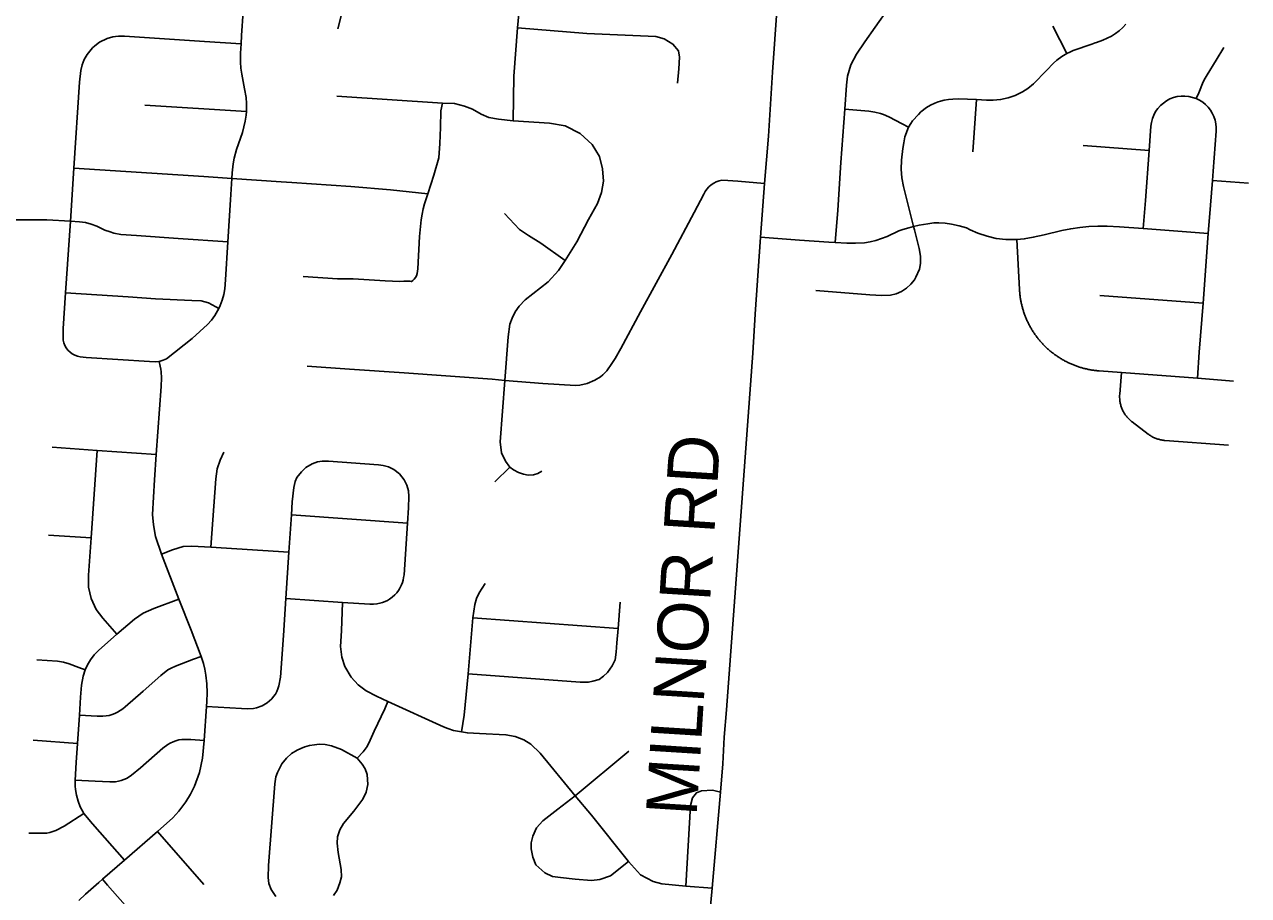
# Model space of a CAD drawing. Extents: x 1880545 to 1948545, y 79309 to 723051.
# Drawn here: x 1895523 to 1902271, y 698000 to 702803 of the extents above; entities that cross this region are included whole.
import ezdxf

# ---------------------------------------------------------------- set-up
doc = ezdxf.new("R2010")
doc.units = 0
for name, color, linetype in [('GM_X_County_Road', 7, 'Continuous'), ('GM_X_Township_Road', 7, 'Continuous'), ('SH_Text', 7, 'Continuous')]:
    doc.layers.add(name, color=color, linetype=linetype)

msp = doc.modelspace()

# ---------------------------------------------------------------- linework, layer by layer
at = {"layer": 'GM_X_County_Road'}
for points in [[(1899603.4, 701926.9), (1899623.9, 702188), (1899647, 702540.4), (1899672.6, 702904.2)], [(1899030.5, 694138.3), (1899059.6, 694602.2), (1899090.3, 695133.9), (1899173.7, 696143.5), (1899230.4, 697129.9), (1899314.5, 698039.5), (1899359.1, 698569.6), (1899373.2, 698725.3), (1899381.1, 698873.1), (1899393.7, 699024.1), (1899474.7, 700118.2), (1899537.6, 700991.2), (1899551.1, 701205.8), (1899581.2, 701630.1), (1899603.4, 701926.9)]]:
    msp.add_lwpolyline(points, dxfattribs=at)
at = {"layer": 'GM_X_Township_Road'}
for p, q in [((1901269.3, 702643.2), (1901191.6, 702794.5)), ((1896187.3, 702358.7), (1896746.2, 702323.2)), ((1900750.9, 702100.6), (1900771.5, 702389.9)), ((1901358.7, 702135), (1901722.7, 702107.4)), ((1896666.1, 701952.9), (1896937.4, 701935.8)), ((1902071.3, 701943.6), (1902270.7, 701928.5)), ((1895444.7, 701725.4), (1895612.2, 701726.5)), ((1901451.5, 701308.7), (1902019.9, 701265.6)), ((1901988.6, 700851.8), (1901999.5, 700996.4)), ((1898115.3, 700280.2), (1898199.4, 700362.2)), ((1896994.4, 700098.3), (1897633.8, 700053.1)), ((1895654.7, 699987.1), (1895890.7, 699971.8)), ((1897994.7, 699531), (1898795.4, 699472.5)), ((1895814.8, 698837.3), (1895571.8, 698855.5)), ((1898558.2, 698548.5), (1898855.5, 698794.8)), ((1896256.2, 698351.9), (1896511.3, 698059.9))]:
    msp.add_line(p, q, dxfattribs=at)
for points in [[(1897251.3, 702779.6), (1897275.9, 702879.9), (1897277.1, 703062.6), (1897287.8, 703187.1), (1897305.4, 703355.7)], [(1898217.4, 702271.2), (1898221.1, 702518.1), (1898241, 702785.2), (1898258.4, 702980.7), (1898269.4, 703137.3), (1898281.1, 703291.3)], [(1899991.3, 701600.3), (1900005.9, 701779.6), (1900022.7, 702042.4), (1900044.5, 702336.3), (1900054.3, 702469.1), (1900060.6, 702518.1), (1900079, 702581.1), (1900109.2, 702639.5), (1900155.1, 702707.8), (1900213.4, 702787.5), (1900288.8, 702895.4)], [(1896265.7, 700945.4), (1896287, 700951.7), (1896305.2, 700960), (1896447.4, 701071.2), (1896532.4, 701147.8), (1896553.2, 701172.4), (1896571.7, 701198.9), (1896593.9, 701236), (1896602.4, 701252.9), (1896613.3, 701282.4), (1896621.5, 701313.9), (1896627, 701345.8), (1896631.7, 701394.5), (1896643.6, 701605), (1896659.6, 701836.7), (1896666.1, 701952.9), (1896667.9, 701984.4), (1896673.2, 702033.7), (1896679.1, 702066.3), (1896691.8, 702114.3), (1896724.5, 702207.4), (1896740.5, 702270.3), (1896744.8, 702302.4), (1896746.2, 702323.2), (1896746.8, 702367.4), (1896744.3, 702399.8), (1896736.8, 702448), (1896720.8, 702528.8), (1896716.3, 702561.6), (1896713.9, 702594.6), (1896713.9, 702644.2), (1896717.1, 702696.8), (1896719.9, 702742.8), (1896729.4, 702873.9)], [(1898241, 702785.2), (1898623.5, 702752.7), (1899003.6, 702736.7), (1899048.9, 702723.5), (1899097.9, 702695.1), (1899128.1, 702657.4), (1899133.8, 702623.5), (1899130, 702559.3), (1899122.4, 702480)], [(1900424.8, 701689.3), (1900368.8, 701908.7), (1900359.5, 701956.6), (1900356.3, 702005.3), (1900358.3, 702054.1), (1900364.8, 702119), (1900369.7, 702151.3), (1900376.7, 702183.1), (1900396.3, 702236.1), (1900408.5, 702257.8), (1900418, 702271.1), (1900450.8, 702307.3), (1900463.7, 702320.5), (1900494.9, 702344.5), (1900516.7, 702357.8), (1900542, 702369.1), (1900559.4, 702376.3), (1900573, 702380.7), (1900592.2, 702385.8), (1900617.4, 702390.1), (1900640.8, 702392.1), (1900671.9, 702392.6), (1900771.5, 702389.9), (1900826.3, 702385.9), (1900862.4, 702385.2), (1900904.2, 702389.1), (1900945.2, 702397.9), (1900984.9, 702411.6), (1901024.4, 702430.9), (1901054.7, 702450.3), (1901085.8, 702475.4), (1901157.5, 702549.7), (1901196.3, 702590.1), (1901214.4, 702606.9), (1901241.7, 702627.1), (1901269.3, 702643.2), (1901289.9, 702652.8), (1901304.8, 702658.7), (1901406.6, 702695.4), (1901425.1, 702702), (1901431.8, 702704.4), (1901468, 702717.5), (1901492.1, 702727.3), (1901515.2, 702739.3), (1901537.2, 702753.1), (1901558, 702768.9), (1901577.2, 702786.3), (1901594.9, 702805.4)], [(1896265.7, 700945.4), (1896244.3, 700943.4), (1896213, 700943.9), (1895862.6, 700966.3), (1895830.6, 700970), (1895815.3, 700973.7), (1895800.7, 700979.3), (1895786.8, 700986.8), (1895774.1, 700996), (1895762.7, 701006.8), (1895753.1, 701019.1), (1895745.6, 701032.7), (1895740.2, 701047.3), (1895737.1, 701062.7), (1895735.8, 701078.6), (1895735.6, 701094.7), (1895736.7, 701127.2), (1895749.9, 701323.6), (1895776.3, 701717.8), (1895795.6, 702010.4), (1895826.2, 702484.4), (1895833.4, 702549.3), (1895840.5, 702580.4), (1895851.9, 702610), (1895867.9, 702637.7), (1895898.4, 702675), (1895910.1, 702685.9), (1895935.8, 702704.8), (1895979.1, 702725.6), (1896009.9, 702734.4), (1896025.7, 702737.1), (1896041.6, 702738.8), (1896073.8, 702739), (1896514.8, 702709.6), (1896717.1, 702696.8)], [(1901982.6, 702394.2), (1901996.3, 702426.6), (1902021.6, 702486.3), (1902031.1, 702506.7), (1902042.2, 702526.3), (1902091.7, 702606.8), (1902133.8, 702675.4)], [(1897244.1, 702408.3), (1897827.6, 702369), (1897894.3, 702367.8), (1897948, 702353.5), (1897993.3, 702336.8), (1898041, 702308.1), (1898082.7, 702290.3), (1898136.4, 702280.7), (1898217.4, 702271.2), (1898416.5, 702259.3), (1898502.9, 702244.5), (1898585.8, 702201.6), (1898652.5, 702141.3)], [(1897650.1, 701387.1), (1897655.9, 701385.2), (1897664.2, 701391), (1897671.5, 701397.7), (1897678.6, 701407), (1897683.5, 701417.5), (1897687.7, 701430), (1897690.2, 701442.9), (1897691, 701455.7), (1897701.2, 701634.7), (1897705.4, 701688.9), (1897709.9, 701726), (1897715.2, 701757.4), (1897721.3, 701786.5), (1897729.1, 701814.7), (1897746.5, 701868.9), (1897780.4, 701971.2), (1897806.4, 702068.1), (1897812.1, 702145.9), (1897815.7, 702234.2), (1897818.1, 702327.2), (1897827.6, 702369)], [(1901690.1, 701677.7), (1901701.9, 701833.2), (1901722.7, 702107.4), (1901732.8, 702242.1), (1901735.7, 702263.2), (1901741.1, 702283.8), (1901748.8, 702303.7), (1901758.8, 702322.5), (1901771, 702340), (1901785.2, 702355.9), (1901801.2, 702370), (1901818.7, 702382.2), (1901837.5, 702392.2), (1901857.4, 702399.9), (1901878, 702405.2), (1901899.2, 702408), (1901920.5, 702408.3), (1901941.7, 702406.1), (1901962.5, 702401.3), (1901982.6, 702394.2)], [(1902060.8, 701806.1), (1902071.3, 701943.6), (1902075.1, 701994.7), (1902091.8, 702214.9), (1902092.2, 702235.2), (1902090.3, 702255.5), (1902086.1, 702275.5), (1902079.7, 702294.8), (1902071.1, 702313.3), (1902060.5, 702330.7), (1902048, 702346.8), (1902033.8, 702361.3), (1902018, 702374.2), (1902000.8, 702385.2), (1901982.6, 702394.2)], [(1900044.5, 702336.3), (1900177.6, 702325.5), (1900210.2, 702320.4), (1900242.2, 702312.4), (1900257.7, 702306.9), (1900287.8, 702293.4), (1900360.8, 702254.9), (1900396.3, 702236.1)], [(1898374.4, 700339.9), (1898353.7, 700326.8), (1898329.9, 700320.2), (1898300.3, 700317.5), (1898273.3, 700322.7), (1898247, 700332.6), (1898218.5, 700346.3), (1898199.4, 700362.2), (1898175, 700395.3), (1898153, 700440.5), (1898144.8, 700500.9), (1898171.5, 700839.7), (1898190.1, 701081), (1898199.4, 701150.6), (1898211, 701184.3), (1898228.4, 701217.9), (1898250.4, 701249.2), (1898284.1, 701284), (1898409.4, 701383.8), (1898466.2, 701446.5), (1898504, 701501.4), (1898567.8, 701605.2), (1898632.8, 701727.6), (1898681.5, 701816.4), (1898704.2, 701876.7), (1898714.6, 701938.8), (1898709.2, 702007), (1898693, 702075.1), (1898652.5, 702141.3)], [(1895795.6, 702010.4), (1896512.3, 701964), (1896666.1, 701952.9)], [(1896937.4, 701935.8), (1896997.1, 701932.1), (1897321.6, 701909), (1897540.5, 701890.4), (1897746.5, 701868.9)], [(1897081.5, 700918.3), (1897314.2, 700902.1), (1897616.9, 700881.4), (1898101.9, 700846.6), (1898171.5, 700839.7), (1898381.3, 700823.2), (1898560.7, 700812.7), (1898584.6, 700814.6), (1898625.2, 700823.9), (1898667.4, 700841.6), (1898698.2, 700860), (1898710.8, 700870.4), (1898733, 700893.6), (1898761.8, 700933), (1898779.3, 700960.8), (1898809.9, 701016.5), (1898918.5, 701217.7), (1899091.4, 701534.4), (1899214, 701766.5), (1899267.5, 701868.1), (1899276, 701882.1), (1899285.5, 701895.4), (1899296.4, 701907.6), (1899308.9, 701918.2), (1899322.4, 701927.6), (1899336.7, 701935.7), (1899352, 701941.3), (1899368.1, 701943.8), (1899399.7, 701943.2), (1899454.9, 701939.6), (1899603.4, 701926.9)], [(1898168.7, 701761.3), (1898252.8, 701672.5), (1898301, 701639.4), (1898368.8, 701596.8), (1898504, 701501.4)], [(1901999.5, 700996.4), (1902019.9, 701265.6), (1902049.1, 701650.5), (1902060.8, 701806.1)], [(1895612.2, 701726.5), (1895645.7, 701726.7), (1895776.3, 701717.8), (1895825.8, 701714.3), (1895858.8, 701710.5), (1895891.3, 701702.8), (1895922.4, 701690.8), (1895966.9, 701669.5), (1895994.9, 701658.7), (1896016.5, 701652.3), (1896055.2, 701645.2), (1896141.4, 701638.8), (1896370.5, 701623.4), (1896643.6, 701605)], [(1899581.2, 701630.1), (1899795.7, 701613.2), (1899958, 701602.3), (1899991.3, 701600.3), (1900055.6, 701596.4), (1900104.3, 701596.3), (1900153.1, 701599.7), (1900185.2, 701605), (1900216.8, 701612.7), (1900278, 701634.8), (1900343.4, 701664.7), (1900365.6, 701673.4), (1900398.7, 701682.4), (1900424.8, 701689.3), (1900455, 701696), (1900502.8, 701703.4), (1900535.6, 701708.4), (1900552.6, 701708.5)], [(1899885.7, 701335.2), (1900182.7, 701312.1), (1900248.5, 701308), (1900297, 701310.9), (1900328.4, 701318.3), (1900358, 701330.8), (1900384.9, 701348.4), (1900408.8, 701370.2), (1900428.9, 701395.7), (1900437.5, 701409.6), (1900457.1, 701454.2), (1900463.1, 701485.4), (1900462.3, 701525.5), (1900455.9, 701568.1), (1900429.7, 701670.4), (1900424.8, 701689.3)], [(1900552.6, 701708.5), (1900564, 701708.6), (1900599.1, 701706.5), (1900633.1, 701702.2), (1900676.5, 701693.1), (1900715.9, 701681.3), (1900735.7, 701670.9), (1900778.1, 701652.8), (1900830.1, 701634.9), (1900878.8, 701623.7), (1900933.4, 701617.1), (1900993.3, 701616.7), (1901034.4, 701620.6), (1901084.2, 701630), (1901143.9, 701643.8)], [(1901143.9, 701643.8), (1901241.4, 701666.3), (1901290.7, 701676.3), (1901340.5, 701683.9), (1901390.6, 701689), (1901440.8, 701691.5), (1901491.2, 701691.5), (1901560, 701687.6), (1901690.1, 701677.7), (1902049.1, 701650.5)], [(1900993.3, 701616.7), (1901008.3, 701340.8), (1901008.9, 701331.3), (1901009.3, 701326.3), (1901009.7, 701321.3), (1901010.2, 701316.3), (1901010.8, 701311.4), (1901011.4, 701306.4), (1901012, 701301.5), (1901012.7, 701296.5), (1901013.5, 701291.6), (1901014.3, 701286.6), (1901015.2, 701281.7), (1901016.1, 701276.8), (1901017.1, 701271.9), (1901018.1, 701267), (1901019.2, 701262.1), (1901020.3, 701257.2), (1901021.5, 701252.4), (1901022.7, 701247.5), (1901024, 701242.7), (1901025.3, 701237.9), (1901026.7, 701233.1), (1901028.1, 701228.3), (1901029.6, 701223.5), (1901031.1, 701218.7), (1901032.7, 701214), (1901034.3, 701209.3), (1901036, 701204.6), (1901037.7, 701199.9), (1901039.5, 701195.2), (1901041.3, 701190.5), (1901043.2, 701185.9), (1901045.1, 701181.3), (1901047.1, 701176.7), (1901049.1, 701172.1), (1901051.2, 701167.6), (1901053.3, 701163.1), (1901055.5, 701158.5), (1901057.7, 701154.1), (1901060, 701149.6), (1901062.3, 701145.2), (1901064.6, 701140.8), (1901067, 701136.4), (1901069.5, 701132), (1901072, 701127.7), (1901074.5, 701123.4), (1901077.1, 701119.1), (1901079.7, 701114.8), (1901082.4, 701110.6), (1901085.1, 701106.4), (1901087.8, 701102.2), (1901090.6, 701098.1), (1901093.5, 701094), (1901096.4, 701089.9), (1901099.3, 701085.9), (1901102.3, 701081.8), (1901105.3, 701077.8), (1901108.4, 701073.9), (1901111.5, 701070), (1901114.6, 701066.1), (1901117.8, 701062.2), (1901121, 701058.4), (1901124.3, 701054.6), (1901127.6, 701050.9), (1901130.9, 701047.1), (1901134.3, 701043.5), (1901137.7, 701039.8), (1901141.2, 701036.2), (1901144.7, 701032.6), (1901148.2, 701029.1), (1901151.8, 701025.6), (1901155.4, 701022.1), (1901159, 701018.7), (1901162.7, 701015.3), (1901166.4, 701012), (1901170.2, 701008.7), (1901174, 701005.4), (1901177.8, 701002.2), (1901181.6, 700999), (1901185.5, 700995.8), (1901189.4, 700992.7), (1901193.4, 700989.6), (1901197.4, 700986.6), (1901201.4, 700983.6), (1901205.4, 700980.7), (1901209.5, 700977.8), (1901213.6, 700975), (1901217.7, 700972.1), (1901221.9, 700969.4), (1901226.1, 700966.7), (1901230.3, 700964), (1901234.6, 700961.4), (1901238.9, 700958.8), (1901243.2, 700956.2), (1901247.5, 700953.7), (1901251.9, 700951.3), (1901256.2, 700948.9), (1901260.6, 700946.5), (1901265.1, 700944.2), (1901269.5, 700941.9), (1901274, 700939.7), (1901278.5, 700937.5), (1901283, 700935.4), (1901287.6, 700933.3), (1901292.2, 700931.3), (1901296.8, 700929.3), (1901301.4, 700927.4), (1901306, 700925.5), (1901310.6, 700923.7), (1901315.3, 700921.9), (1901320, 700920.2), (1901324.7, 700918.5), (1901329.4, 700916.8), (1901334.2, 700915.3), (1901338.9, 700913.7), (1901343.7, 700912.2), (1901348.5, 700910.8), (1901353.3, 700909.4), (1901358.1, 700908.1), (1901363, 700906.8), (1901367.8, 700905.6), (1901372.7, 700904.4), (1901377.5, 700903.2), (1901382.4, 700902.2), (1901387.3, 700901.1), (1901392.2, 700900.2), (1901397.1, 700899.2), (1901402, 700898.4), (1901407, 700897.5), (1901411.9, 700896.8), (1901416.9, 700896), (1901421.8, 700895.4), (1901426.8, 700894.8), (1901431.8, 700894.2), (1901436.7, 700893.7), (1901441.7, 700893.2), (1901446.7, 700892.8), (1901569.8, 700883.5), (1901988.6, 700851.8), (1902188, 700836.7)], [(1897059.5, 701412.8), (1897249.3, 701401.2), (1897335.3, 701400.2), (1897511.5, 701388.8), (1897593.1, 701385.8), (1897614.2, 701387.1), (1897650.1, 701387.1)], [(1895749.9, 701323.6), (1896094.5, 701301), (1896245.1, 701291), (1896446.1, 701281), (1896496.7, 701278.4), (1896518.1, 701273.7), (1896537, 701267.9), (1896558.4, 701257.6), (1896577.2, 701246.2), (1896593.9, 701236)], [(1895823.6, 697971.8), (1895859.3, 698006.2), (1895933.4, 698071.5), (1895953.6, 698089), (1896074.6, 698194.1), (1896256.2, 698351.9), (1896340.4, 698428.6), (1896373.7, 698464.4), (1896412.8, 698516.4), (1896438, 698558.2), (1896460, 698601.9), (1896488.1, 698678.2), (1896504, 698757.8), (1896513.5, 698854.6), (1896526, 699041.5), (1896527.8, 699068.8), (1896529.4, 699117.8), (1896528, 699166.7), (1896522.9, 699215.3), (1896517.2, 699247.3), (1896509.5, 699278.9), (1896497, 699318), (1896441.8, 699463.4), (1896374.8, 699634.5), (1896277.9, 699882.4), (1896246.3, 699979.2), (1896234.2, 700043.3), (1896228.8, 700101), (1896239.8, 700291.3), (1896249.9, 700432.1), (1896276.9, 700805.9), (1896278.5, 700854.8), (1896277, 700887), (1896274.5, 700902.9), (1896271, 700918.7), (1896265.7, 700945.4)], [(1901569.8, 700883.5), (1901560.7, 700763.7), (1901560.3, 700756.4), (1901560.2, 700751.4), (1901560.3, 700746.4), (1901560.6, 700739.2), (1901561, 700734.2), (1901561.5, 700729.2), (1901562.2, 700724.3), (1901563, 700719.4), (1901564, 700714.5), (1901565.1, 700709.6), (1901566.3, 700704.7), (1901567.7, 700699.9), (1901569.2, 700695.2), (1901570.8, 700690.4), (1901572.6, 700685.8), (1901574.5, 700681.1), (1901576.6, 700676.6), (1901578.7, 700672.1), (1901581.1, 700667.6), (1901583.5, 700663.3), (1901586, 700659), (1901588.7, 700654.8), (1901591.5, 700650.6), (1901594.4, 700646.5), (1901597.4, 700642.6), (1901600.6, 700638.7), (1901603.8, 700634.9), (1901607.2, 700631.2), (1901610.6, 700627.6), (1901614.2, 700624.1), (1901617.9, 700620.6), (1901621.6, 700617.3), (1901625.5, 700614.2), (1901629.4, 700611.1), (1901717.3, 700544.4), (1901721.6, 700541.2), (1901725.7, 700538.4), (1901729.9, 700535.7), (1901734.2, 700533.1), (1901738.5, 700530.6), (1901742.9, 700528.2), (1901747.4, 700526), (1901751.9, 700523.9), (1901756.5, 700522), (1901761.2, 700520.1), (1901765.9, 700518.4), (1901770.6, 700516.9), (1901775.4, 700515.4), (1901780.3, 700514.1), (1901785.1, 700513), (1901790, 700512), (1901794.9, 700511.1), (1901799.9, 700510.4), (1901804.9, 700509.8), (1901809.8, 700509.3), (1902161.2, 700482.7)], [(1895676.3, 700471.6), (1895924.7, 700454.4), (1896249.9, 700432.1)], [(1896032.1, 699440.3), (1895954.8, 699528.8), (1895918.8, 699577.6), (1895890.4, 699636.7), (1895876.2, 699700.8), (1895875.7, 699766.4), (1895890.7, 699971.8), (1895924.7, 700454.4)], [(1896551.1, 699921.2), (1896577.6, 700297.8), (1896585.8, 700352.8), (1896601.1, 700399.7), (1896622.3, 700444.6)], [(1896994.4, 700098.3), (1896999.6, 700170.5), (1897007.3, 700250.1), (1897015.1, 700281.9), (1897025.4, 700304), (1897049.7, 700336.9), (1897073.4, 700359.3), (1897108.3, 700380.5), (1897139.3, 700390.4), (1897163.6, 700394.1), (1897199.6, 700394.1), (1897473.8, 700375.1), (1897499.5, 700371.4), (1897529.8, 700363.9), (1897559.1, 700349.7), (1897591.1, 700324.2), (1897616.4, 700291.6), (1897631.3, 700262.5), (1897639.3, 700231.1), (1897642.1, 700199.8), (1897640.3, 700138.5), (1897633.8, 700053.1), (1897615.3, 699768.8), (1897613, 699752.5), (1897610.1, 699738.7), (1897606.4, 699725.7), (1897601.1, 699712.3), (1897596.5, 699701.6), (1897590.7, 699691.2), (1897585.4, 699682.4), (1897575.5, 699669.6), (1897564.1, 699657.6), (1897549.6, 699644.2), (1897535.7, 699634.2), (1897523.6, 699626.9), (1897511.4, 699620.7), (1897497.2, 699615.3), (1897482.9, 699611.1), (1897466.3, 699608), (1897447.9, 699605.7), (1897427.1, 699606.3), (1897277, 699616.4), (1896963.8, 699637.9)], [(1896526, 699041.5), (1896720.2, 699030.1), (1896753.1, 699029.2), (1896785.9, 699031.7), (1896802.1, 699034.9), (1896833.2, 699045.6), (1896861.7, 699062.1), (1896874.5, 699072.4), (1896886.2, 699083.9), (1896896.7, 699096.5), (1896906, 699110.2), (1896913.9, 699124.6), (1896920.6, 699139.7), (1896926, 699155.2), (1896935.1, 699203.7), (1896950.1, 699433.8), (1896963.8, 699637.9), (1896981, 699892.5), (1896994.4, 700098.3)], [(1896277.9, 699882.4), (1896338.5, 699905.9), (1896397.3, 699924.2), (1896445.9, 699927.1), (1896551.1, 699921.2), (1896981, 699892.5)], [(1897932.2, 698901.6), (1897947.4, 698994), (1897969, 699222.6), (1897994.7, 699531), (1898005.4, 699604.5), (1898015.1, 699638.4), (1898029.6, 699668.6), (1898062.2, 699719.4)], [(1896074.6, 698194.1), (1895897.5, 698394.4), (1895851.2, 698452.6), (1895846.3, 698459.5), (1895830.4, 698489), (1895818.4, 698520.1), (1895809.4, 698552.2), (1895803.7, 698585.1), (1895802.4, 698601.8), (1895802.5, 698635), (1895807.7, 698733.6), (1895814.8, 698837.3), (1895825.6, 698994.8), (1895832.4, 699094), (1895837.9, 699159.7), (1895846.4, 699208.9), (1895857.9, 699243.8), (1895870.4, 699271.1), (1895887.5, 699299.8), (1895907.6, 699326.4), (1895930.6, 699350.6), (1896032.1, 699440.3), (1896129.1, 699523.5), (1896177.3, 699556.1), (1896235.6, 699581.7), (1896374.8, 699634.5)], [(1897277, 699616.4), (1897270.3, 699459.3), (1897265.9, 699373.8), (1897271.8, 699313.3), (1897289.5, 699261.7), (1897324.9, 699203.4), (1897363.2, 699161.4), (1897407.5, 699128.2), (1897463.5, 699099.5), (1897526.6, 699070.5), (1897832.2, 698929.9), (1897856.3, 698921), (1897888.3, 698909.2), (1897932.2, 698901.6), (1897964.9, 698895.9), (1898031.3, 698892.9), (1898177, 698886.1), (1898228.2, 698876.8), (1898276.1, 698857.6), (1898314.4, 698834), (1898366.7, 698784.4), (1898558.2, 698548.5), (1898648.2, 698442.5), (1898852, 698186.6), (1898918.9, 698114.4), (1898988.6, 698077.3), (1899035.8, 698064.3), (1899169.1, 698051.9), (1899314.5, 698039.5)], [(1897969, 699222.6), (1898586.7, 699176.9), (1898631.5, 699176.1), (1898655.6, 699181), (1898691.3, 699191.8), (1898714.6, 699208.4), (1898737.8, 699229.2), (1898763.6, 699265.7), (1898778.5, 699299), (1898785.1, 699341.3), (1898789.3, 699393.6), (1898795.4, 699472.5), (1898806.7, 699617.8)], [(1895825.6, 698994.8), (1895923, 698989.4), (1895955.5, 698988.8), (1895973, 698989.9), (1895989.6, 698992.9), (1896005.9, 698997.5), (1896021.6, 699003.7), (1896036.7, 699011.1), (1896064.8, 699029.3), (1896077.8, 699039.7), (1896176.5, 699126.6), (1896274.9, 699213.4), (1896314.1, 699243.4), (1896331.8, 699254.3), (1896356.5, 699264.7), (1896455.7, 699302.3), (1896497, 699318)], [(1895857.9, 699243.8), (1895822.4, 699257.7), (1895769.7, 699278.1), (1895738.1, 699286.5), (1895705.9, 699291.5), (1895591.4, 699299.3)], [(1897357.3, 698757.2), (1897390.1, 698791.7), (1897413.1, 698821.3), (1897429.6, 698855.8), (1897451.7, 698905.1), (1897509.2, 699030), (1897526.6, 699070.5)], [(1895802.5, 698635), (1895912.7, 698630.5), (1895993.5, 698626.4), (1896025.5, 698627.4), (1896041.2, 698629.8), (1896056.5, 698633.7), (1896071.5, 698639), (1896085.9, 698645.7), (1896099.7, 698653.6), (1896112.8, 698662.7), (1896162.5, 698704.7), (1896285.8, 698812.2), (1896312.5, 698832), (1896326.9, 698840.5), (1896342.2, 698847.7), (1896358, 698853.3), (1896374.3, 698857.3), (1896390.9, 698859.8), (1896407.6, 698860.7), (1896440.8, 698859.8), (1896513.5, 698854.6)], [(1897357.3, 698757.2), (1897270.5, 698804.6), (1897216.3, 698824.3), (1897180.2, 698832.6), (1897147.3, 698834.2), (1897121, 698830.9), (1897094.7, 698827.6), (1897068.4, 698819.4), (1897047.1, 698811.2), (1897025.9, 698800.6), (1896994.5, 698783.2), (1896968.2, 698757), (1896941.9, 698725.8), (1896917.3, 698678.1), (1896909.1, 698653.5), (1896902.5, 698615.7), (1896868, 698165.5), (1896866.4, 698099.8), (1896869.7, 698065.3), (1896882.8, 698032.4), (1896909.1, 697994.6)], [(1897225.8, 697999.6), (1897247.5, 698029.1), (1897262.3, 698070.2), (1897270.5, 698103.1), (1897268.9, 698142.5), (1897252.4, 698236.2), (1897247.5, 698288.7), (1897249.2, 698323.2), (1897260.7, 698362.7), (1897282, 698397.2), (1897339.5, 698464.5), (1897388.8, 698530.2), (1897406.9, 698569.7), (1897416.7, 698612.4), (1897411.8, 698666.6), (1897402, 698697.8), (1897385.5, 698724.1), (1897357.3, 698757.2)], [(1899169.1, 698051.9), (1899195.5, 698495.7), (1899204.8, 698537.8), (1899227.2, 698565.1), (1899254.5, 698577.8), (1899316, 698579.8), (1899359.1, 698569.6)], [(1898852, 698186.6), (1898754.2, 698108.5), (1898694.3, 698087.5), (1898649.1, 698082.9), (1898558.6, 698089.4), (1898478.4, 698098.6), (1898434.1, 698104.1), (1898392.5, 698124.4), (1898342.7, 698169.7), (1898326.1, 698210.3), (1898316, 698257.3), (1898316, 698289.6), (1898325.2, 698326.6), (1898345.5, 698372.7), (1898381.5, 698411.5), (1898462.7, 698475.2), (1898558.2, 698548.5)], [(1895851.2, 698452.6), (1895741.5, 698382.3), (1895696.5, 698358.2), (1895663.8, 698347.4), (1895646.9, 698344.2), (1895629.7, 698342.7), (1895547.4, 698343.8)], [(1896230.5, 697773.1), (1895981.1, 698057.6), (1895953.6, 698089)]]:
    msp.add_lwpolyline(points, dxfattribs=at)

# ---------------------------------------------------------------- texts
at = {"layer": 'SH_Text'}
msp.add_text('MILNOR RD', height=280, rotation=86.40079, dxfattribs=at).set_placement((1899227.8, 698434.2))

doc.saveas('drawing.dxf')
